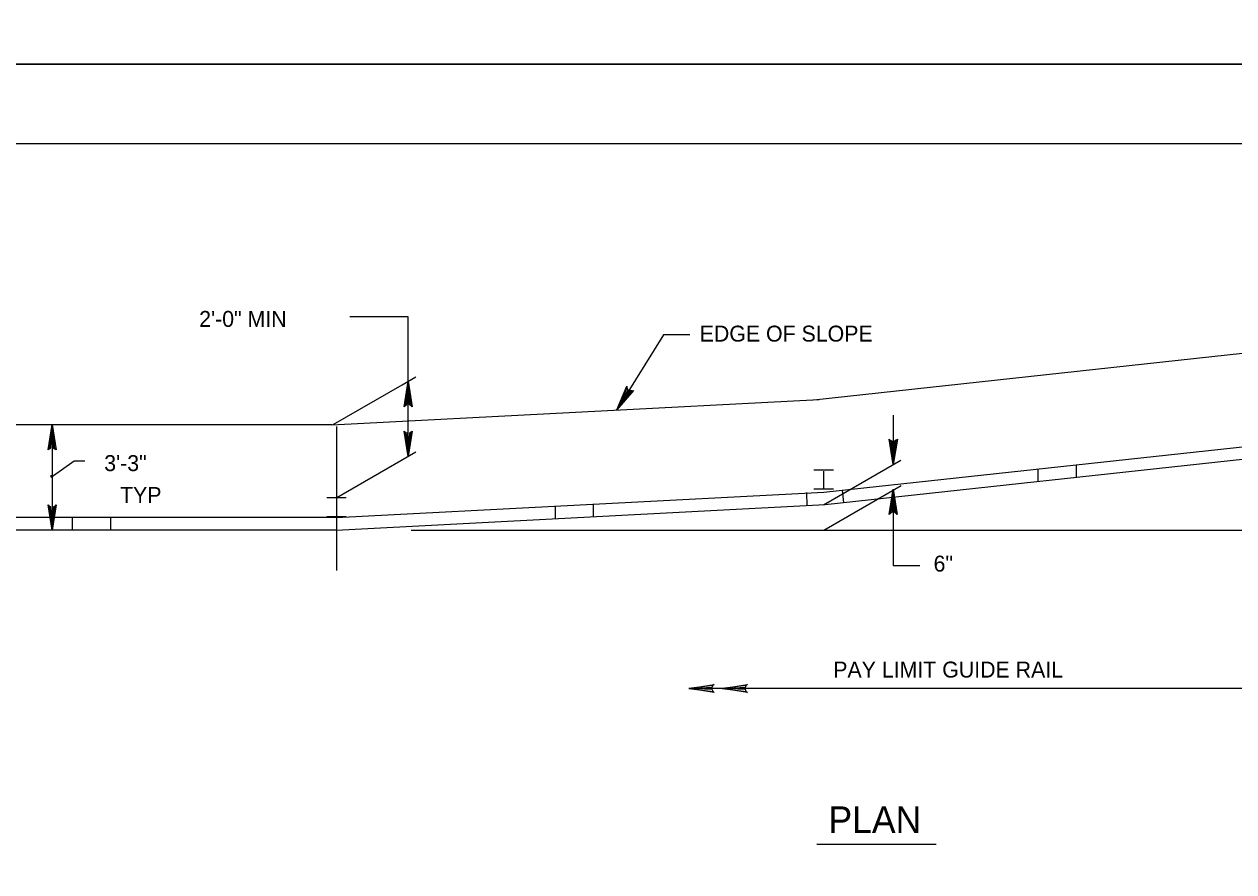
# Model space of a CAD drawing. Extents: x 637628 to 640188, y 298266 to 300751.
# Drawn here: x 638654 to 638881.6, y 298707.5 to 298867.1 of the extents above; entities that cross this region are included whole.
import ezdxf

# ---------------------------------------------------------------- set-up
doc = ezdxf.new("R2010")
doc.units = 0
for name, color, linetype in [('1', 7, 'Continuous'), ('2', 7, 'Continuous'), ('3', 7, 'Continuous'), ('PLT-BNDY', 7, 'Continuous')]:
    doc.layers.add(name, color=color, linetype=linetype)

msp = doc.modelspace()

# ---------------------------------------------------------------- linework, layer by layer
at = {"layer": '1'}
msp.add_lwpolyline([(639104.52, 298280.58), (639104.52, 298844.55), (638318.55, 298844.55), (638318.55, 298280.58), (639104.52, 298280.58), (639104.52, 298306.93), (638904.53, 298306.93), (638904.53, 298371.61), (639104.52, 298371.61), (639104.52, 298400.57), (638904.53, 298400.57), (638904.53, 298280.58), (638983.33, 298280.58), (638983.33, 298306.93), (638983.33, 298280.58), (639060.33, 298280.58), (639060.33, 298306.93), (639060.33, 298294.62), (639104.52, 298294.62)], dxfattribs=at)
at = {"layer": '2'}
for p, q in [((638726.25, 298811.98), (638715.25, 298811.98)), ((638726.25, 298785.74), (638726.25, 298811.98)), ((638802.61, 298796.38), (638888.87, 298805.76)), ((638712.13, 298791.71), (638725.11, 298799.2)), ((638725.11, 298799.2), (638727.7, 298800.7)), ((638711.87, 298791.68), (638803.59, 298796.46)), ((638817.54, 298793.49), (638817.54, 298784.22)), ((638525.21, 298791.71), (638711.87, 298791.71)), ((638659.26, 298791.71), (638659.26, 298771.84)), ((638712.84, 298777.99), (638712.84, 298791.39)), ((638804.5, 298778.98), (638890.76, 298788.36)), ((638712.84, 298777.99), (638727.7, 298786.57)), ((638804.75, 298776.7), (638891.01, 298786.08)), ((638802.61, 298783.18), (638806.26, 298783.18)), ((638804.38, 298776.62), (638818.94, 298785.04)), ((638844.76, 298783.36), (638844.76, 298781.05)), ((638851.93, 298784.14), (638851.93, 298781.83)), ((638804.47, 298779.61), (638804.47, 298782.93)), ((638712.78, 298774.21), (638804.5, 298778.98)), ((638801.23, 298778.91), (638801.3, 298776.4)), ((638802.61, 298779.61), (638806.26, 298779.61)), ((638804.47, 298771.84), (638819.04, 298780.25)), ((638807.95, 298779.4), (638808.16, 298777.05)), ((638710.94, 298777.99), (638714.6, 298777.99)), ((638712.68, 298771.84), (638804.75, 298776.7)), ((638712.84, 298774.42), (638712.84, 298777.99)), ((638712.84, 298764.26), (638712.84, 298777.99)), ((638753.9, 298776.35), (638753.9, 298774.02)), ((638761.08, 298776.72), (638761.08, 298774.39)), ((638712.78, 298774.21), (638600.83, 298774.21)), ((638663.06, 298774.21), (638663.06, 298771.84)), ((638670.23, 298774.21), (638670.23, 298771.84)), ((638710.94, 298774.42), (638714.6, 298774.42)), ((638712.68, 298771.84), (638600.54, 298771.84)), ((638726.82, 298771.84), (639080.01, 298771.84)), ((638726.96, 298771.84), (638892.87, 298771.84)), ((638817.54, 298765.22), (638822.54, 298765.22)), ((638793.01, 298742.07), (638779.08, 298742.07)), ((638890.37, 298742.07), (638793.01, 298742.07))]:
    msp.add_line(p, q, dxfattribs=at)
for points in [[(638779.28, 298808.59), (638774.28, 298808.59), (638765.5, 298794.51)], [(638725.68, 298795.32), (638726.01, 298795.49), (638726.25, 298799.86), (638725.68, 298795.32), (638725.48, 298795.09), (638726.25, 298799.86), (638726.47, 298795.49), (638726.79, 298795.34), (638726.25, 298799.86), (638727.01, 298795.09), (638726.79, 298795.34)], [(638768.38, 298798.06), (638768.02, 298798.1), (638765.5, 298794.51), (638768.38, 298798.06), (638768.68, 298798.16), (638765.5, 298794.51), (638767.63, 298798.33), (638767.43, 298798.64), (638765.5, 298794.51), (638767.38, 298798.96), (638767.43, 298798.64)], [(638658.69, 298787.17), (638659.02, 298787.34), (638659.26, 298791.71), (638658.69, 298787.17), (638658.49, 298786.94), (638659.26, 298791.71), (638659.48, 298787.34), (638659.8, 298787.18), (638659.26, 298791.71), (638660.02, 298786.94), (638659.8, 298787.18)], [(638726.82, 298790.28), (638726.49, 298790.11), (638726.25, 298785.74), (638726.82, 298790.28), (638727.02, 298790.51), (638726.25, 298785.74), (638726.04, 298790.1), (638725.71, 298790.26), (638726.25, 298785.74), (638725.49, 298790.51), (638725.71, 298790.26)], [(638818.11, 298788.76), (638817.78, 298788.6), (638817.54, 298784.22), (638818.11, 298788.76), (638818.31, 298789), (638817.54, 298784.22), (638817.33, 298788.59), (638817, 298788.75), (638817.54, 298784.22), (638816.78, 298789), (638817, 298788.75)], [(638665.4, 298784.86), (638663.41, 298784.86), (638659.06, 298781.74)], [(638816.97, 298775.04), (638817.3, 298775.21), (638817.54, 298779.58), (638816.97, 298775.04), (638816.77, 298774.81), (638817.54, 298779.58), (638817.76, 298775.21), (638818.08, 298775.05), (638817.54, 298779.58), (638818.3, 298774.81), (638818.08, 298775.05)], [(638817.54, 298779.58), (638817.54, 298765.22)], [(638659.83, 298776.38), (638659.5, 298776.21), (638659.26, 298771.84), (638659.83, 298776.38), (638660.03, 298776.61), (638659.26, 298771.84), (638659.04, 298776.21), (638658.72, 298776.37), (638659.26, 298771.84), (638658.5, 298776.61), (638658.72, 298776.37)], [(638783.62, 298741.5), (638783.45, 298741.83), (638779.08, 298742.07), (638783.62, 298741.5), (638783.85, 298741.3), (638779.08, 298742.07), (638783.45, 298742.29), (638783.61, 298742.61), (638779.08, 298742.07), (638783.85, 298742.83), (638783.61, 298742.61)], [(638789.87, 298741.5), (638789.7, 298741.83), (638785.33, 298742.07), (638789.87, 298741.5), (638790.1, 298741.3), (638785.33, 298742.07), (638789.7, 298742.29), (638789.86, 298742.61), (638785.33, 298742.07), (638790.1, 298742.83), (638789.86, 298742.61)]]:
    msp.add_lwpolyline(points, dxfattribs=at)
at = {"layer": '3'}
msp.add_line((638803.16, 298712.76), (638825.62, 298712.76), dxfattribs=at)
at = {"layer": 'PLT-BNDY'}
for points in [[(638278.52, 299453.58), (639119.52, 299453.58), (639119.52, 298859.58), (638278.52, 298859.58)], [(638278.52, 298859.58), (639119.52, 298859.58), (639119.52, 298265.58), (638278.52, 298265.58)]]:
    msp.add_lwpolyline(points, close=True, dxfattribs=at)

# ---------------------------------------------------------------- texts
at = {"layer": '3'}
for s, height, p in [('2\'-0" MIN', 3, (638686.93, 298810.11)), ('EDGE OF SLOPE', 3, (638781.11, 298807.34)), ('3\'-3"', 3, (638669.06, 298782.97)), ('TYP', 3, (638672.04, 298776.97)), ('6"', 3, (638825.12, 298764.05)), ('PAY LIMIT GUIDE RAIL', 3, (638806.24, 298744.11)), ('PLAN', 5, (638805.34, 298714.86))]:
    msp.add_text(s, height=height, dxfattribs=at).set_placement(p)
msp.add_text('.', height=3, rotation=180, dxfattribs=at).set_placement((638659.64, 298782.25))

doc.saveas('drawing.dxf')
